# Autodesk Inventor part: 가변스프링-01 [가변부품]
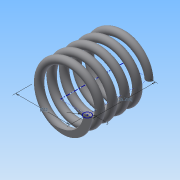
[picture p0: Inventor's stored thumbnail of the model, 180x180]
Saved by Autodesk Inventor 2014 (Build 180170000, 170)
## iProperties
Created: 2015-09
Part Number: 가변스프링-01 [가변부품]
Material: 강철, 탄소
Document SubType Name: Modeling
Designer: study
Density: 7.87 g/cm^3
Appearance: 반연마
Mass: 18.8856 g
Surface Area: 32.5491 cm^2
Volume: 2.3997 cm^3
Author: study
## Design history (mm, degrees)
sketch "스케치1"
  geometry: L1 (0, 0)-(11, 0); L2 (11, 0)-(11, 36.411); L3 (11, 36.411)-(0, 36.411); L4 (0, 36.411)-(0, 0); C1 r 1.5 at (11, 0)
  constraints: 8 end point, 2 parallel, 1 centre point, 1 coincident, 1 horizontal, 1 perpendicular
  dimensions: "d0" = 36.4112 distance of L1.end L2.end (derived); "d1" = 22 diameter of L2 L4; "d2" = 3 diameter of C1
feature "코일1" sketch "스케치1" pitch "d3" = 10; turns "d5" = 5; dims "d4" = 36.4112 (= d0), "d6" = 0, angle "d7" = 90 deg, angle "d8" = 90 deg, "d9" = 0, "d10" = 0
node "작업 평면1"
sketch "스케치2"
  geometry: L1 (-12.5, 0)-(-9.5, 0) reference; 1 further point
  constraints: 1 horizontal alignment
extrude "돌출1" cut sketch "스케치2" stored distance "d12" = 10; taper "d13" = 0 deg
node "작업 평면2"
sketch "스케치3"
  geometry: L1 (-9.5, 0)-(-12.5, 0) reference; 1 further point
  constraints: 1 horizontal alignment
extrude "돌출2" cut sketch "스케치3" stored distance "d15" = 10; taper "d16" = 0 deg
node "솔리드1"
node "절단 모서리 투영1"
node "절단 모서리 투영2"
other parameters: "d11" = 0, "d14" = 36.4112 (= d0)
